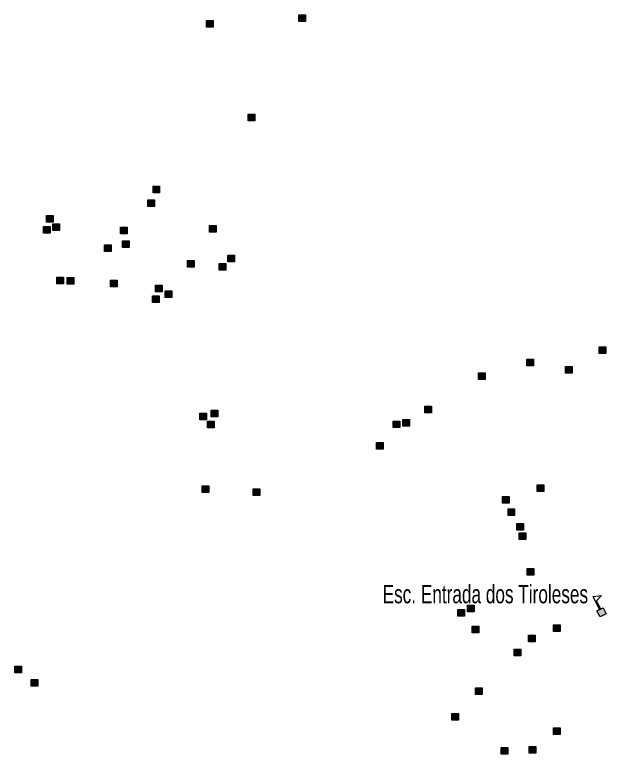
# Model space of a CAD drawing. Extents: x 649.2 to 674.4, y 7040 to 7068.1.
# Drawn here: x 668.171 to 670.747, y 7040.25 to 7043.471 of the extents above; entities that cross this region are included whole.
import ezdxf
from ezdxf.enums import TextEntityAlignment as Align

# ---------------------------------------------------------------- set-up
doc = ezdxf.new("R2010")
doc.units = 0
doc.header["$LTSCALE"] = 0.032
doc.layers.add('2', color=7, linetype='Continuous', lineweight=25)
doc.layers.add('4', color=7, linetype='Continuous', lineweight=25)
doc.layers.add('61', color=7, linetype='Continuous')

msp = doc.modelspace()

# ---------------------------------------------------------------- hatches: boundary and pattern name
at = {"layer": '2'}
for points in [[(669.4082, 7043.4706), (669.4372, 7043.4706), (669.4372, 7043.4416), (669.4082, 7043.4416)], [(669.0059, 7043.4457), (669.0349, 7043.4457), (669.0349, 7043.4167), (669.0059, 7043.4167)], [(669.1873, 7043.0381), (669.2163, 7043.0381), (669.2163, 7043.0091), (669.1873, 7043.0091)], [(668.7727, 7042.7235), (668.8017, 7042.7235), (668.8017, 7042.6945), (668.7727, 7042.6945)], [(668.7505, 7042.665), (668.7795, 7042.665), (668.7795, 7042.636), (668.7505, 7042.636)], [(668.3094, 7042.5968), (668.3384, 7042.5968), (668.3384, 7042.5678), (668.3094, 7042.5678)], [(668.3362, 7042.5595), (668.3652, 7042.5595), (668.3652, 7042.5305), (668.3362, 7042.5305)], [(668.2956, 7042.549), (668.3246, 7042.549), (668.3246, 7042.52), (668.2956, 7042.52)], [(668.6315, 7042.5449), (668.6605, 7042.5449), (668.6605, 7042.5159), (668.6315, 7042.5159)], [(669.0187, 7042.5534), (669.0477, 7042.5534), (669.0477, 7042.5244), (669.0187, 7042.5244)], [(668.5609, 7042.4678), (668.5899, 7042.4678), (668.5899, 7042.4388), (668.5609, 7042.4388)], [(668.6396, 7042.4857), (668.6686, 7042.4857), (668.6686, 7042.4567), (668.6396, 7042.4567)], [(668.9231, 7042.4006), (668.9521, 7042.4006), (668.9521, 7042.3716), (668.9231, 7042.3716)], [(669.0994, 7042.4237), (669.1284, 7042.4237), (669.1284, 7042.3947), (669.0994, 7042.3947)], [(669.0611, 7042.3874), (669.0901, 7042.3874), (669.0901, 7042.3584), (669.0611, 7042.3584)], [(668.354, 7042.3275), (668.383, 7042.3275), (668.383, 7042.2985), (668.354, 7042.2985)], [(668.3995, 7042.3259), (668.4285, 7042.3259), (668.4285, 7042.2969), (668.3995, 7042.2969)], [(668.5869, 7042.3145), (668.6159, 7042.3145), (668.6159, 7042.2855), (668.5869, 7042.2855)], [(668.7839, 7042.2921), (668.8129, 7042.2921), (668.8129, 7042.2631), (668.7839, 7042.2631)], [(668.8254, 7042.268), (668.8544, 7042.268), (668.8544, 7042.239), (668.8254, 7042.239)], [(668.7706, 7042.2469), (668.7996, 7042.2469), (668.7996, 7042.2179), (668.7706, 7042.2179)], [(670.7164, 7042.0238), (670.7454, 7042.0238), (670.7454, 7041.9948), (670.7164, 7041.9948)], [(670.4014, 7041.9699), (670.4304, 7041.9699), (670.4304, 7041.9409), (670.4014, 7041.9409)], [(670.5696, 7041.9387), (670.5986, 7041.9387), (670.5986, 7041.9097), (670.5696, 7041.9097)], [(670.19, 7041.9103), (670.219, 7041.9103), (670.219, 7041.8813), (670.19, 7041.8813)], [(669.9571, 7041.766), (669.9861, 7041.766), (669.9861, 7041.737), (669.9571, 7041.737)], [(668.9767, 7041.7354), (669.0057, 7041.7354), (669.0057, 7041.7064), (668.9767, 7041.7064)], [(669.0264, 7041.7481), (669.0554, 7041.7481), (669.0554, 7041.7191), (669.0264, 7041.7191)], [(669.0108, 7041.7009), (669.0398, 7041.7009), (669.0398, 7041.6719), (669.0108, 7041.6719)], [(669.8193, 7041.7011), (669.8483, 7041.7011), (669.8483, 7041.6721), (669.8193, 7041.6721)], [(669.8605, 7041.7081), (669.8895, 7041.7081), (669.8895, 7041.6791), (669.8605, 7041.6791)], [(669.7464, 7041.6072), (669.7754, 7041.6072), (669.7754, 7041.5782), (669.7464, 7041.5782)], [(668.9872, 7041.4193), (669.0162, 7041.4193), (669.0162, 7041.3903), (668.9872, 7041.3903)], [(669.2086, 7041.4057), (669.2376, 7041.4057), (669.2376, 7041.3767), (669.2086, 7041.3767)], [(670.4457, 7041.4236), (670.4747, 7041.4236), (670.4747, 7041.3946), (670.4457, 7041.3946)], [(670.2958, 7041.3728), (670.3248, 7041.3728), (670.3248, 7041.3438), (670.2958, 7041.3438)], [(670.3192, 7041.3178), (670.3482, 7041.3178), (670.3482, 7041.2888), (670.3192, 7041.2888)], [(670.3577, 7041.2546), (670.3867, 7041.2546), (670.3867, 7041.2256), (670.3577, 7041.2256)], [(670.3673, 7041.2133), (670.3963, 7041.2133), (670.3963, 7041.1843), (670.3673, 7041.1843)], [(670.4031, 7041.058), (670.4321, 7041.058), (670.4321, 7041.029), (670.4031, 7041.029)], [(670.1433, 7040.8986), (670.1723, 7040.8986), (670.1723, 7040.8696), (670.1433, 7040.8696)], [(670.1007, 7040.8793), (670.1297, 7040.8793), (670.1297, 7040.8503), (670.1007, 7040.8503)], [(670.1625, 7040.8078), (670.1915, 7040.8078), (670.1915, 7040.7788), (670.1625, 7040.7788)], [(670.5171, 7040.8133), (670.5461, 7040.8133), (670.5461, 7040.7843), (670.5171, 7040.7843)], [(670.4086, 7040.768), (670.4376, 7040.768), (670.4376, 7040.739), (670.4086, 7040.739)], [(670.3464, 7040.7074), (670.3754, 7040.7074), (670.3754, 7040.6784), (670.3464, 7040.6784)], [(668.1706, 7040.6327), (668.1996, 7040.6327), (668.1996, 7040.6037), (668.1706, 7040.6037)], [(668.2421, 7040.5748), (668.2711, 7040.5748), (668.2711, 7040.5458), (668.2421, 7040.5458)], [(670.1774, 7040.5384), (670.2064, 7040.5384), (670.2064, 7040.5094), (670.1774, 7040.5094)], [(670.0746, 7040.4273), (670.1036, 7040.4273), (670.1036, 7040.3983), (670.0746, 7040.3983)], [(670.5175, 7040.3642), (670.5465, 7040.3642), (670.5465, 7040.3352), (670.5175, 7040.3352)], [(670.2893, 7040.2786), (670.3183, 7040.2786), (670.3183, 7040.2496), (670.2893, 7040.2496)], [(670.4109, 7040.2831), (670.4399, 7040.2831), (670.4399, 7040.2541), (670.4109, 7040.2541)]]:
    msp.add_hatch(color=256, dxfattribs=at).paths.add_polyline_path(points)
at = {"layer": '4'}
msp.add_hatch(color=256, dxfattribs=at).paths.add_polyline_path([(670.7201, 7040.8476), (670.7067, 7040.8745), (670.7336, 7040.8879), (670.747, 7040.861)])

# ---------------------------------------------------------------- linework, layer by layer
at = {"layer": '2'}
for points in [[(669.4082, 7043.4706), (669.4372, 7043.4706), (669.4372, 7043.4416), (669.4082, 7043.4416)], [(669.0059, 7043.4457), (669.0349, 7043.4457), (669.0349, 7043.4167), (669.0059, 7043.4167)], [(669.1873, 7043.0381), (669.2163, 7043.0381), (669.2163, 7043.0091), (669.1873, 7043.0091)], [(668.7727, 7042.7235), (668.8017, 7042.7235), (668.8017, 7042.6945), (668.7727, 7042.6945)], [(668.7505, 7042.665), (668.7795, 7042.665), (668.7795, 7042.636), (668.7505, 7042.636)], [(668.3094, 7042.5968), (668.3384, 7042.5968), (668.3384, 7042.5678), (668.3094, 7042.5678)], [(668.3362, 7042.5595), (668.3652, 7042.5595), (668.3652, 7042.5305), (668.3362, 7042.5305)], [(668.2956, 7042.549), (668.3246, 7042.549), (668.3246, 7042.52), (668.2956, 7042.52)], [(668.6315, 7042.5449), (668.6605, 7042.5449), (668.6605, 7042.5159), (668.6315, 7042.5159)], [(669.0187, 7042.5534), (669.0477, 7042.5534), (669.0477, 7042.5244), (669.0187, 7042.5244)], [(668.5609, 7042.4678), (668.5899, 7042.4678), (668.5899, 7042.4388), (668.5609, 7042.4388)], [(668.6396, 7042.4857), (668.6686, 7042.4857), (668.6686, 7042.4567), (668.6396, 7042.4567)], [(668.9231, 7042.4006), (668.9521, 7042.4006), (668.9521, 7042.3716), (668.9231, 7042.3716)], [(669.0994, 7042.4237), (669.1284, 7042.4237), (669.1284, 7042.3947), (669.0994, 7042.3947)], [(669.0611, 7042.3874), (669.0901, 7042.3874), (669.0901, 7042.3584), (669.0611, 7042.3584)], [(668.354, 7042.3275), (668.383, 7042.3275), (668.383, 7042.2985), (668.354, 7042.2985)], [(668.3995, 7042.3259), (668.4285, 7042.3259), (668.4285, 7042.2969), (668.3995, 7042.2969)], [(668.5869, 7042.3145), (668.6159, 7042.3145), (668.6159, 7042.2855), (668.5869, 7042.2855)], [(668.7839, 7042.2921), (668.8129, 7042.2921), (668.8129, 7042.2631), (668.7839, 7042.2631)], [(668.8254, 7042.268), (668.8544, 7042.268), (668.8544, 7042.239), (668.8254, 7042.239)], [(668.7706, 7042.2469), (668.7996, 7042.2469), (668.7996, 7042.2179), (668.7706, 7042.2179)], [(670.7164, 7042.0238), (670.7454, 7042.0238), (670.7454, 7041.9948), (670.7164, 7041.9948)], [(670.4014, 7041.9699), (670.4304, 7041.9699), (670.4304, 7041.9409), (670.4014, 7041.9409)], [(670.5696, 7041.9387), (670.5986, 7041.9387), (670.5986, 7041.9097), (670.5696, 7041.9097)], [(670.19, 7041.9103), (670.219, 7041.9103), (670.219, 7041.8813), (670.19, 7041.8813)], [(669.9571, 7041.766), (669.9861, 7041.766), (669.9861, 7041.737), (669.9571, 7041.737)], [(668.9767, 7041.7354), (669.0057, 7041.7354), (669.0057, 7041.7064), (668.9767, 7041.7064)], [(669.0264, 7041.7481), (669.0554, 7041.7481), (669.0554, 7041.7191), (669.0264, 7041.7191)], [(669.0108, 7041.7009), (669.0398, 7041.7009), (669.0398, 7041.6719), (669.0108, 7041.6719)], [(669.8193, 7041.7011), (669.8483, 7041.7011), (669.8483, 7041.6721), (669.8193, 7041.6721)], [(669.8605, 7041.7081), (669.8895, 7041.7081), (669.8895, 7041.6791), (669.8605, 7041.6791)], [(669.7464, 7041.6072), (669.7754, 7041.6072), (669.7754, 7041.5782), (669.7464, 7041.5782)], [(668.9872, 7041.4193), (669.0162, 7041.4193), (669.0162, 7041.3903), (668.9872, 7041.3903)], [(669.2086, 7041.4057), (669.2376, 7041.4057), (669.2376, 7041.3767), (669.2086, 7041.3767)], [(670.4457, 7041.4236), (670.4747, 7041.4236), (670.4747, 7041.3946), (670.4457, 7041.3946)], [(670.2958, 7041.3728), (670.3248, 7041.3728), (670.3248, 7041.3438), (670.2958, 7041.3438)], [(670.3192, 7041.3178), (670.3482, 7041.3178), (670.3482, 7041.2888), (670.3192, 7041.2888)], [(670.3577, 7041.2546), (670.3867, 7041.2546), (670.3867, 7041.2256), (670.3577, 7041.2256)], [(670.3673, 7041.2133), (670.3963, 7041.2133), (670.3963, 7041.1843), (670.3673, 7041.1843)], [(670.4031, 7041.058), (670.4321, 7041.058), (670.4321, 7041.029), (670.4031, 7041.029)], [(670.1433, 7040.8986), (670.1723, 7040.8986), (670.1723, 7040.8696), (670.1433, 7040.8696)], [(670.1007, 7040.8793), (670.1297, 7040.8793), (670.1297, 7040.8503), (670.1007, 7040.8503)], [(670.1625, 7040.8078), (670.1915, 7040.8078), (670.1915, 7040.7788), (670.1625, 7040.7788)], [(670.5171, 7040.8133), (670.5461, 7040.8133), (670.5461, 7040.7843), (670.5171, 7040.7843)], [(670.4086, 7040.768), (670.4376, 7040.768), (670.4376, 7040.739), (670.4086, 7040.739)], [(670.3464, 7040.7074), (670.3754, 7040.7074), (670.3754, 7040.6784), (670.3464, 7040.6784)], [(668.1706, 7040.6327), (668.1996, 7040.6327), (668.1996, 7040.6037), (668.1706, 7040.6037)], [(668.2421, 7040.5748), (668.2711, 7040.5748), (668.2711, 7040.5458), (668.2421, 7040.5458)], [(670.1774, 7040.5384), (670.2064, 7040.5384), (670.2064, 7040.5094), (670.1774, 7040.5094)], [(670.0746, 7040.4273), (670.1036, 7040.4273), (670.1036, 7040.3983), (670.0746, 7040.3983)], [(670.5175, 7040.3642), (670.5465, 7040.3642), (670.5465, 7040.3352), (670.5175, 7040.3352)], [(670.2893, 7040.2786), (670.3183, 7040.2786), (670.3183, 7040.2496), (670.2893, 7040.2496)], [(670.4109, 7040.2831), (670.4399, 7040.2831), (670.4399, 7040.2541), (670.4109, 7040.2541)]]:
    msp.add_lwpolyline(points, close=True, dxfattribs=at)
at = {"layer": '4'}
msp.add_line((670.7179, 7040.8801), (670.7224, 7040.8823), dxfattribs=at)
for points in [[(670.7179, 7040.8801), (670.69, 7040.936), (670.7269, 7040.9404), (670.7048, 7040.9176), (670.7224, 7040.8823)], [(670.7201, 7040.8476), (670.7067, 7040.8745), (670.7336, 7040.8879), (670.747, 7040.861)]]:
    msp.add_lwpolyline(points, close=True, dxfattribs=at)

# ---------------------------------------------------------------- texts
at = {"layer": '61', "width": 0.7}
msp.add_text('Esc. Entrada dos Tiroleses', height=0.08, dxfattribs=at).set_placement((670.6679, 7040.907), align=Align.RIGHT)

doc.saveas('drawing.dxf')
